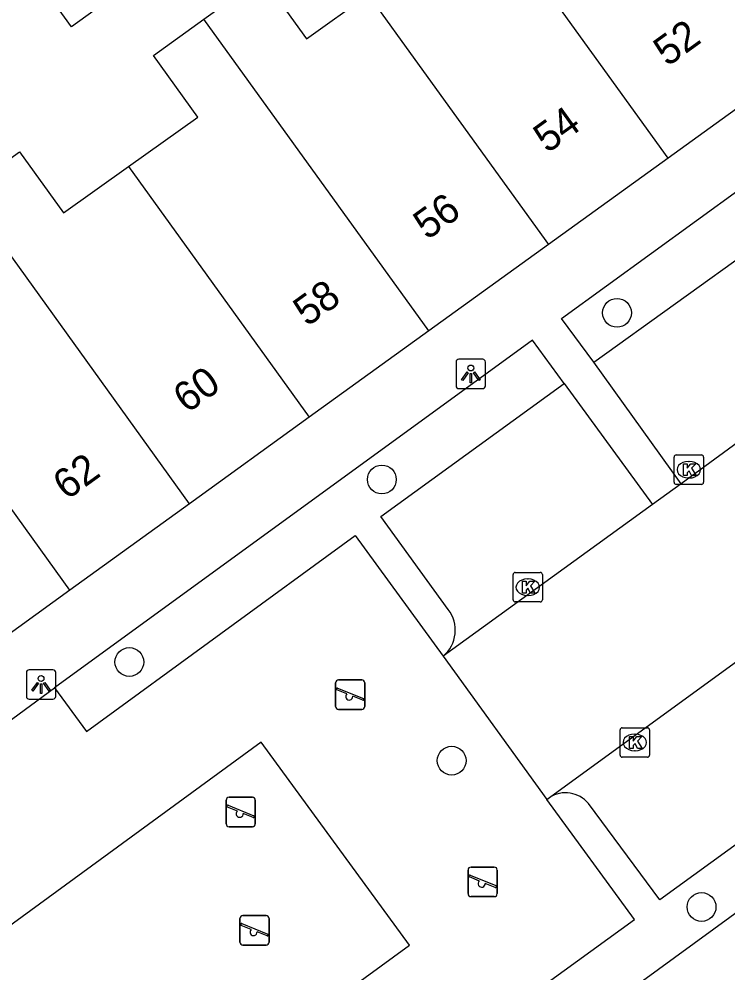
# Model space of a CAD drawing. Extents: x 159822 to 160765, y 380693 to 381634.
# Drawn here: x 159945.21 to 159969.28, y 381278.23 to 381310.61 of the extents above; entities that cross this region are included whole.
import ezdxf

# ---------------------------------------------------------------- set-up
doc = ezdxf.new("R2010")
doc.units = 0
for name, color, linetype in [('IMGEO_Boom', 7, 'Continuous'), ('IMGEO_Kolk', 7, 'Continuous'), ('IMGEO_Lichtpunt', 7, 'Continuous'), ('IMGEO_Pand', 7, 'Continuous'), ('IMGEO_Pand_nummerreeks', 7, 'Continuous'), ('IMGEO_Parkeervlak_open', 7, 'Continuous'), ('IMGEO_Rijbaan_lokaal_open', 7, 'Continuous'), ('IMGEO_Speelvoorziening', 7, 'Continuous'), ('IMGEO_Voetpad_open', 7, 'Continuous')]:
    doc.layers.add(name, color=color, linetype=linetype)

msp = doc.modelspace()

# ---------------------------------------------------------------- linework, layer by layer
at = {"layer": 'IMGEO_Boom'}
for centre in [(159965.511, 381300.638), (159957.526, 381294.98), (159948.953, 381288.783), (159959.895, 381285.435), (159968.382, 381280.469)]:
    msp.add_circle(centre, 0.489, dxfattribs=at)
at = {"layer": 'IMGEO_Kolk'}
for p, q in [((159967.523, 381295.812), (159968.375, 381295.812)), ((159967.448, 381294.886), (159967.448, 381295.738)), ((159967.936, 381295.592), (159967.961, 381295.592)), ((159968.449, 381295.738), (159968.449, 381294.886)), ((159968.375, 381294.812), (159967.523, 381294.812)), ((159967.959, 381295.032), (159967.934, 381295.032)), ((159961.979, 381290.898), (159961.979, 381291.75)), ((159962.054, 381291.824), (159962.906, 381291.824)), ((159962.467, 381291.604), (159962.492, 381291.604)), ((159962.98, 381291.75), (159962.98, 381290.898)), ((159962.49, 381291.044), (159962.465, 381291.044)), ((159962.906, 381290.824), (159962.054, 381290.824)), ((159965.614, 381285.627), (159965.614, 381286.479)), ((159965.689, 381286.553), (159966.541, 381286.553)), ((159966.615, 381286.479), (159966.615, 381285.627)), ((159966.102, 381286.333), (159966.127, 381286.333)), ((159966.125, 381285.773), (159966.1, 381285.773)), ((159966.541, 381285.553), (159965.689, 381285.553))]:
    msp.add_line(p, q, dxfattribs=at)
for points in [[(159967.523, 381295.812), (159968.375, 381295.812)], [(159967.448, 381294.886), (159967.448, 381295.738)], [(159967.769, 381295.512), (159967.892, 381295.512), (159967.892, 381295.361), (159968.022, 381295.512), (159968.186, 381295.512), (159968.04, 381295.361), (159968.193, 381295.112), (159968.041, 381295.112), (159967.956, 381295.276), (159967.892, 381295.209), (159967.892, 381295.112), (159967.769, 381295.112), (159967.769, 381295.512)], [(159968.449, 381295.738), (159968.449, 381294.886)], [(159968.375, 381294.812), (159967.523, 381294.812)], [(159961.979, 381290.898), (159961.979, 381291.75)], [(159962.054, 381291.824), (159962.906, 381291.824)], [(159962.98, 381291.75), (159962.98, 381290.898)], [(159962.3, 381291.524), (159962.423, 381291.524), (159962.423, 381291.373), (159962.553, 381291.524), (159962.717, 381291.524), (159962.571, 381291.373), (159962.724, 381291.124), (159962.572, 381291.124), (159962.487, 381291.288), (159962.423, 381291.221), (159962.423, 381291.124), (159962.3, 381291.124), (159962.3, 381291.524)], [(159962.906, 381290.824), (159962.054, 381290.824)], [(159965.614, 381285.627), (159965.614, 381286.479)], [(159965.689, 381286.553), (159966.541, 381286.553)], [(159966.615, 381286.479), (159966.615, 381285.627)], [(159965.935, 381286.253), (159966.058, 381286.253), (159966.058, 381286.102), (159966.188, 381286.253), (159966.352, 381286.253), (159966.206, 381286.102), (159966.359, 381285.853), (159966.207, 381285.853), (159966.122, 381286.017), (159966.058, 381285.95), (159966.058, 381285.853), (159965.935, 381285.853), (159965.935, 381286.253)], [(159966.541, 381285.553), (159965.689, 381285.553)]]:
    msp.add_lwpolyline(points, dxfattribs=at)
for centre, start, end in [((159967.525, 381295.736), 91.552, 178.448), ((159967.525, 381295.736), 91.552, 178.448), ((159968.373, 381295.736), 1.552, 88.448), ((159968.373, 381295.736), 1.552, 88.448), ((159967.525, 381294.888), 181.552, 268.448), ((159967.525, 381294.888), 181.552, 268.448), ((159968.373, 381294.888), 271.552, 358.448), ((159968.373, 381294.888), 271.552, 358.448), ((159962.056, 381291.748), 91.552, 178.448), ((159962.056, 381291.748), 91.552, 178.448), ((159962.904, 381291.748), 1.552, 88.448), ((159962.904, 381291.748), 1.552, 88.448), ((159962.056, 381290.9), 181.552, 268.448), ((159962.056, 381290.9), 181.552, 268.448), ((159962.904, 381290.9), 271.552, 358.448), ((159962.904, 381290.9), 271.552, 358.448), ((159965.691, 381286.477), 91.552, 178.448), ((159965.691, 381286.477), 91.552, 178.448), ((159966.539, 381286.477), 1.552, 88.448), ((159966.539, 381286.477), 1.552, 88.448), ((159965.691, 381285.629), 181.552, 268.448), ((159965.691, 381285.629), 181.552, 268.448), ((159966.539, 381285.629), 271.552, 358.448), ((159966.539, 381285.629), 271.552, 358.448)]:
    msp.add_arc(centre, 0.0765, start, end, dxfattribs=at)
for centre, major_axis, ratio, start_param, end_param in [((159967.935, 381295.312), (-0.387, 0.002), 0.722429, 4.712389, 7.853982), ((159967.96, 381295.312), (-0.39, 0.002), 0.717154, 1.570796, 4.712389), ((159962.466, 381291.324), (-0.387, 0.002), 0.722429, 4.712389, 7.853982), ((159962.491, 381291.324), (-0.39, 0.002), 0.717154, 1.570796, 4.712389), ((159966.101, 381286.053), (-0.387, 0.002), 0.722429, 4.712389, 7.853982), ((159966.126, 381286.053), (-0.39, 0.002), 0.717154, 1.570796, 4.712389)]:
    msp.add_ellipse(centre, major_axis=major_axis, ratio=ratio, start_param=start_param, end_param=end_param, dxfattribs=at)
at = {"layer": 'IMGEO_Lichtpunt'}
for p, q in [((159960.949, 381299.062), (159960.141, 381299.062)), ((159960.949, 381299.062), (159960.141, 381299.062)), ((159960.047, 381298.967), (159960.047, 381298.16)), ((159960.047, 381298.967), (159960.047, 381298.16)), ((159961.043, 381298.16), (159961.043, 381298.967)), ((159961.043, 381298.16), (159961.043, 381298.967)), ((159960.141, 381298.066), (159960.949, 381298.066)), ((159960.141, 381298.066), (159960.949, 381298.066)), ((159945.455, 381288.425), (159945.455, 381287.618)), ((159945.455, 381288.425), (159945.455, 381287.618)), ((159946.357, 381288.52), (159945.549, 381288.52)), ((159946.357, 381288.52), (159945.549, 381288.52)), ((159946.451, 381287.618), (159946.451, 381288.425)), ((159946.451, 381287.618), (159946.451, 381288.425)), ((159945.549, 381287.524), (159946.357, 381287.524)), ((159945.549, 381287.524), (159946.357, 381287.524))]:
    msp.add_line(p, q, dxfattribs=at)
for points in [[(159960.421, 381298.631), (159960.46, 381298.603), (159960.272, 381298.341), (159960.234, 381298.368), (159960.421, 381298.631)], [(159960.523, 381298.583), (159960.57, 381298.583), (159960.57, 381298.261), (159960.523, 381298.261), (159960.523, 381298.583)], [(159960.633, 381298.603), (159960.671, 381298.63), (159960.858, 381298.368), (159960.819, 381298.34), (159960.633, 381298.603)], [(159945.829, 381288.089), (159945.868, 381288.061), (159945.68, 381287.799), (159945.642, 381287.826), (159945.829, 381288.089)], [(159945.931, 381288.041), (159945.978, 381288.041), (159945.978, 381287.719), (159945.931, 381287.719), (159945.931, 381288.041)], [(159946.041, 381288.061), (159946.079, 381288.088), (159946.266, 381287.826), (159946.227, 381287.798), (159946.041, 381288.061)]]:
    msp.add_lwpolyline(points, dxfattribs=at)
for centre in [(159960.546, 381298.765), (159945.954, 381288.223)]:
    msp.add_circle(centre, 0.0994, dxfattribs=at)
for centre, start, end in [((159960.141, 381298.967), 90, 180), ((159960.141, 381298.967), 90, 180), ((159960.949, 381298.967), 0, 90), ((159960.949, 381298.967), 0, 90), ((159960.141, 381298.16), 180, 270), ((159960.141, 381298.16), 180, 270), ((159960.949, 381298.16), 270, 0), ((159960.949, 381298.16), 270, 360), ((159945.549, 381288.425), 90, 180), ((159945.549, 381288.425), 90, 180), ((159946.357, 381288.425), 0, 90), ((159946.357, 381288.425), 0, 90), ((159945.549, 381287.618), 180, 270), ((159945.549, 381287.618), 180, 270), ((159946.357, 381287.618), 270, 0), ((159946.357, 381287.618), 270, 360)]:
    msp.add_arc(centre, 0.0946, start, end, dxfattribs=at)
at = {"layer": 'IMGEO_Pand'}
for points in [[(159967.247, 381305.886), (159959.614, 381316.461)], [(159948.312, 381314.75), (159949.947, 381312.481), (159946.989, 381310.348), (159945.381, 381312.581)], [(159951.483, 381310.609), (159953.459, 381312.034), (159954.972, 381309.937), (159957.059, 381311.442)], [(159957.059, 381311.442), (159958.797, 381309.033), (159963.185, 381302.954)], [(159948.918, 381305.601), (159951.279, 381307.278), (159949.768, 381309.373), (159951.483, 381310.609)], [(159959.123, 381300.023), (159951.483, 381310.609)], [(159971.406, 381308.887), (159967.247, 381305.886)], [(159943.352, 381304.754), (159945.227, 381306.106), (159946.718, 381304.038), (159948.918, 381305.601)], [(159967.247, 381305.886), (159963.185, 381302.954)], [(159948.918, 381305.601), (159950.673, 381303.17), (159955.06, 381297.091)], [(159950.998, 381294.159), (159943.352, 381304.754)], [(159963.185, 381302.954), (159959.123, 381300.023)], [(159959.123, 381300.023), (159955.06, 381297.091)], [(159946.936, 381291.228), (159942.552, 381297.303), (159940.804, 381299.726)], [(159955.06, 381297.091), (159950.998, 381294.159)], [(159950.998, 381294.159), (159946.936, 381291.228)], [(159946.936, 381291.228), (159942.874, 381288.296)]]:
    msp.add_lwpolyline(points, dxfattribs=at)
at = {"layer": 'IMGEO_Parkeervlak_open'}
for points in [[(159964.722, 381298.96), (159973.039, 381304.942), (159975.38, 381301.732)], [(159959.776, 381290.572), (159957.49, 381293.728), (159963.72, 381298.234)], [(159973.189, 381285.226), (159966.968, 381280.709), (159964.543, 381283.979)]]:
    msp.add_lwpolyline(points, dxfattribs=at)
for centre, radius, start, end in [((159958.872, 381289.865), 1.148, 309.6377, 38.0219), ((159963.765, 381283.334), 1.01, 39.6387, 122.7715)]:
    msp.add_arc(centre, radius, start, end, dxfattribs=at)
at = {"layer": 'IMGEO_Rijbaan_lokaal_open'}
for points in [[(159976.746, 381301.467), (159967.693, 381294.838)], [(159967.693, 381294.838), (159966.715, 381294.128)], [(159966.715, 381294.128), (159959.604, 381288.981)], [(159959.604, 381288.981), (159963.13, 381284.119)], [(159963.218, 381284.184), (159970.234, 381289.284)], [(159963.13, 381284.119), (159963.218, 381284.184)]]:
    msp.add_lwpolyline(points, dxfattribs=at)
at = {"layer": 'IMGEO_Speelvoorziening'}
for p, q in [((159955.954, 381287.274), (159955.954, 381288.074)), ((159955.954, 381288.074), (159955.954, 381287.274)), ((159956.054, 381288.174), (159956.844, 381288.174)), ((159956.844, 381288.174), (159956.054, 381288.174)), ((159956.944, 381288.074), (159956.944, 381287.274)), ((159956.944, 381287.274), (159956.944, 381288.074)), ((159956.337, 381287.702), (159955.998, 381287.839)), ((159956.023, 381287.899), (159956.899, 381287.546)), ((159956.875, 381287.486), (159956.535, 381287.623)), ((159956.844, 381287.174), (159956.054, 381287.174)), ((159956.054, 381287.174), (159956.844, 381287.174)), ((159952.338, 381284.194), (159953.128, 381284.194)), ((159953.128, 381284.194), (159952.338, 381284.194)), ((159952.238, 381283.294), (159952.238, 381284.094)), ((159952.238, 381284.094), (159952.238, 381283.294)), ((159952.621, 381283.722), (159952.282, 381283.859)), ((159952.307, 381283.919), (159953.183, 381283.566)), ((159953.228, 381284.094), (159953.228, 381283.294)), ((159953.228, 381283.294), (159953.228, 381284.094)), ((159953.159, 381283.506), (159952.819, 381283.643)), ((159953.128, 381283.194), (159952.338, 381283.194)), ((159952.338, 381283.194), (159953.128, 381283.194)), ((159960.453, 381280.921), (159960.453, 381281.721)), ((159960.453, 381281.721), (159960.453, 381280.921)), ((159960.522, 381281.546), (159961.398, 381281.193)), ((159960.553, 381281.821), (159961.343, 381281.821)), ((159961.343, 381281.821), (159960.553, 381281.821)), ((159961.443, 381281.721), (159961.443, 381280.921)), ((159961.443, 381280.921), (159961.443, 381281.721)), ((159960.836, 381281.349), (159960.497, 381281.486)), ((159961.374, 381281.133), (159961.034, 381281.27)), ((159961.343, 381280.821), (159960.553, 381280.821)), ((159960.553, 381280.821), (159961.343, 381280.821)), ((159952.707, 381279.277), (159952.707, 381280.077)), ((159952.707, 381280.077), (159952.707, 381279.277)), ((159952.776, 381279.902), (159953.652, 381279.549)), ((159952.807, 381280.177), (159953.597, 381280.177)), ((159953.597, 381280.177), (159952.807, 381280.177)), ((159953.697, 381280.077), (159953.697, 381279.277)), ((159953.697, 381279.277), (159953.697, 381280.077)), ((159953.09, 381279.705), (159952.751, 381279.842)), ((159953.628, 381279.489), (159953.288, 381279.626)), ((159953.597, 381279.177), (159952.807, 381279.177)), ((159952.807, 381279.177), (159953.597, 381279.177))]:
    msp.add_line(p, q, dxfattribs=at)
for centre, radius, start, end in [((159956.054, 381288.074), 0.1, 90, 180), ((159956.054, 381288.074), 0.1, 90, 180), ((159956.844, 381288.074), 0.1, 0, 90), ((159956.844, 381288.074), 0.1, 360, 90), ((159956.011, 381287.869), 0.0327, 68.078, 248.078), ((159956.416, 381287.612), 0.12, 130.9928, 5.1632), ((159956.887, 381287.516), 0.0327, 248.078, 68.078), ((159956.054, 381287.274), 0.1, 180, 270), ((159956.054, 381287.274), 0.1, 180, 270), ((159956.844, 381287.274), 0.1, 270, 0), ((159956.844, 381287.274), 0.1, 270, 0), ((159952.338, 381284.094), 0.1, 90, 180), ((159952.338, 381284.094), 0.1, 90, 180), ((159953.128, 381284.094), 0.1, 0, 90), ((159953.128, 381284.094), 0.1, 360, 90), ((159952.295, 381283.889), 0.0327, 68.078, 248.078), ((159952.7, 381283.632), 0.12, 130.9928, 5.1632), ((159953.171, 381283.536), 0.0327, 248.078, 68.078), ((159952.338, 381283.294), 0.1, 180, 270), ((159952.338, 381283.294), 0.1, 180, 270), ((159953.128, 381283.294), 0.1, 270, 0), ((159953.128, 381283.294), 0.1, 270, 0), ((159960.553, 381281.721), 0.1, 90, 180), ((159960.553, 381281.721), 0.1, 90, 180), ((159960.51, 381281.516), 0.0327, 68.078, 248.078), ((159961.343, 381281.721), 0.1, 0, 90), ((159961.343, 381281.721), 0.1, 360, 90), ((159960.915, 381281.259), 0.12, 130.9928, 5.1632), ((159961.386, 381281.163), 0.0327, 248.078, 68.078), ((159960.553, 381280.921), 0.1, 180, 270), ((159960.553, 381280.921), 0.1, 180, 270), ((159961.343, 381280.921), 0.1, 270, 0), ((159961.343, 381280.921), 0.1, 270, 0), ((159952.807, 381280.077), 0.1, 90, 180), ((159952.807, 381280.077), 0.1, 90, 180), ((159952.764, 381279.872), 0.0327, 68.078, 248.078), ((159953.597, 381280.077), 0.1, 0, 90), ((159953.597, 381280.077), 0.1, 360, 90), ((159953.169, 381279.615), 0.12, 130.9928, 5.1632), ((159952.807, 381279.277), 0.1, 180, 270), ((159952.807, 381279.277), 0.1, 180, 270), ((159953.597, 381279.277), 0.1, 270, 0), ((159953.597, 381279.277), 0.1, 270, 0), ((159953.64, 381279.519), 0.0327, 248.078, 68.078)]:
    msp.add_arc(centre, radius, start, end, dxfattribs=at)
at = {"layer": 'IMGEO_Voetpad_open'}
for points in [[(159964.722, 381298.96), (159963.625, 381300.445), (159972.788, 381307.097)], [(159963.72, 381298.234), (159962.646, 381299.714), (159946.408, 381287.912)], [(159967.693, 381294.838), (159964.722, 381298.96)], [(159963.72, 381298.234), (159966.715, 381294.128)], [(159946.408, 381287.912), (159947.492, 381286.426), (159956.615, 381293.074), (159959.604, 381288.981)], [(159943.953, 381286.112), (159946.408, 381287.912)], [(159953.428, 381286.065), (159943.829, 381279.059), (159948.891, 381272.191), (159958.469, 381279.172), (159953.428, 381286.065)], [(159973.189, 381285.226), (159974.309, 381283.732), (159957.647, 381271.588)], [(159957.647, 381271.588), (159956.554, 381273.113), (159966.101, 381280.048), (159963.13, 381284.119)]]:
    msp.add_lwpolyline(points, dxfattribs=at)

# ---------------------------------------------------------------- texts
at = {"layer": 'IMGEO_Pand_nummerreeks'}
for s, p in [('52', (159967.22, 381308.974)), ('54', (159963.143, 381306.032)), ('56', (159959.065, 381303.088)), ('58', (159954.989, 381300.147)), ('60', (159950.911, 381297.204)), ('62', (159946.828, 381294.258))]:
    msp.add_text(s, height=1, rotation=35.8169, dxfattribs=at).set_placement(p)

doc.saveas('drawing.dxf')
